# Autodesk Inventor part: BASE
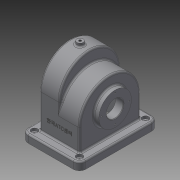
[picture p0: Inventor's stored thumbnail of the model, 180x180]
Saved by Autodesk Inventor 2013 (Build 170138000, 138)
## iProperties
Created: 2017-11
Part Number: BASE
Material: 일반
Document SubType Name: Modeling
Designer: Administrator
Density: 1 g/cm^3
Author: Administrator
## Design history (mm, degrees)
sketch "스케치1"
  geometry: L1 (-58, 0)-(-58, -65); L2 (-58, -65)-(58, -65); L3 (58, -65)-(58, 0); A1 r 58 centre (0, 0) between (58, 0) and (-58, 0); 1 further point
  constraints: 6 end point, 2 point on circle, 2 tangent, 1 centre point, 1 coincident, 1 perpendicular, 1 vertical, 1 vertical alignment
  dimensions: "d0" = 116 diameter of A1; "d3" = 65 distance of L1.start L1.end
extrude "돌출1" new body sketch "스케치1" distance "d4" = 38; taper "d5" = 0 deg
sketch "스케치2"
  geometry: L1 (0, 58)-(65, 58) reference; L2 (65, 58)-(65, -58) reference; L3 (65, -58)-(0, -58) reference; L4 (65, -58)-(65, 58); L5 (65, 58)-(23, 58); L6 (55.666, -58)-(23, -58); L7 (55.666, -58)-(65, -58); A1 r 58 centre (0, 0) between (0, 58) and (0, -58) reference; A2 r 58 centre (23, 0) between (23, 58) and (23, -58); 1 further point
  constraints: 8 end point, 2 collinear, 2 point on circle, 2 tangent, 1 centre point, 1 horizontal alignment, 1 point on line, 1 vertical alignment
  dimensions: "d6" = 116 diameter of A2; "d8" = 42 distance from line of L2 A2.centre
extrude "돌출2" join sketch "스케치2" distance "d9" = 38; taper "d10" = 0 deg
feature "쉘1" dims "d11" = 5
sketch "스케치4"
  geometry: L1 (-71, 111)-(-71, 5) reference; L2 (-71, 5)-(-5, 5) reference; L3 (-5, 5)-(-5, 111) reference; L4 (-5, 111)-(-71, 111) reference; L5 (-76, 0)-(-76, 116) reference; L6 (-76, 116)-(0, 116) reference; L7 (0, 116)-(0, 0) reference; L8 (0, 0)-(-76, 0) reference; L9 (17, 133)-(-93, 133); L10 (-93, 133)-(-93, -17); L11 (-93, -17)-(17, -17); L12 (17, -17)-(17, 133); 1 further point
  constraints: 8 end point, 3 other
  dimensions: "d12" = 110 distance of L9.start L9.end; "d14" = 150 distance of L9.end L10.end (derived)
extrude "돌출3" join sketch "스케치4" distance "d15" = 15; taper "d16" = 0 deg
fillet "모깎기1" dims "d17" = 12
sketch "스케치7"
  geometry: L1 (-80, 75)-(-65, 75) reference; L2 (-65, 75)-(-65, 58) reference; L3 (-65, 58)-(-65, -58) reference; L4 (-65, -58)-(-65, -75) reference; L5 (-65, -75)-(-80, -75) reference; L6 (-80, -75)-(-80, 75) reference; L7 (-65, 58)-(0, 58) reference; L8 (0, -58)-(-65, -58) reference; C1 r 37.5 at (-15, 0); A1 r 58 centre (0, 0) between (0, -58) and (0, 58) reference; 1 further point
  constraints: 1 centre point, 1 horizontal alignment
  dimensions: "d18" = 75 diameter of C1; "d20" = 65 distance from line of L6 C1.centre
extrude "돌출4" join sketch "스케치7" distance "d21" = 9; taper "d22" = 0 deg
sketch "스케치8"
  geometry: L1 (23, 58)-(65, 58) reference; L2 (65, 58)-(65, 75) reference; L3 (65, 75)-(80, 75) reference; L4 (80, 75)-(80, -75) reference; L5 (80, -75)-(65, -75) reference; L6 (65, -75)-(65, -58) reference; L7 (65, -58)-(65, 58) reference; L8 (65, -58)-(23, -58) reference; C1 r 31 at (15, 0); A1 r 58 centre (23, 0) between (23, 58) and (23, -58) reference; 1 further point
  constraints: 1 centre point, 1 horizontal alignment
  dimensions: "d23" = 62 diameter of C1; "d25" = 65 distance from line of L4 C1.centre
extrude "돌출5" join sketch "스케치8" distance "d26" = 10; taper "d27" = 0 deg
sketch "스케치9"
  geometry: L1 (50, -73.909)-(50, 73.909) reference; L2 (50, 73.909)-(65, 73.909) reference; L3 (65, 73.909)-(65, -73.909) reference; L4 (65, -73.909)-(50, -73.909) reference; C1 r 31 at (0, 0) reference; C2 r 16 at (0, 0); 1 further point
  constraints: 1 centre point, 1 coincident
  dimensions: "d28" = 32 diameter of C2
extrude "돌출6" cut sketch "스케치9" stored distance "d30" = 10; taper "d31" = 0 deg
chamfer "모따기1" distance "d32" = 1; stored, may be unused: second distance "d33" = 2, angle "d34" = 45 deg
fillet "모깎기2" dims "d35" = 3
fillet "모깎기3" dims "d36" = 3
hole "구멍1" diameter "d39" = 5; stored, may be unused: countersink angle "d43" = 90 deg, drill point angle "d45" = 118 deg; dims "d37" = 10, "d38" = 10, "d40" = 6, "d41" = 12, "d42" = 5, "d44" = 8
node "작업 평면1"
sketch "스케치11"
  geometry: L1 (55, -66.317)-(55, -59.683) reference; L2 (55, -59.683)-(50, -59.683) reference; L3 (50, -59.683)-(50, 59.683) reference; L4 (50, 59.683)-(55, 59.683) reference; L5 (55, 59.683)-(55, 66.317) reference; L6 (55, 66.317)-(50, 66.317) reference; L7 (50, 66.317)-(50, 73.909) reference; L8 (50, 73.909)-(65, 73.909) reference; L9 (65, 73.909)-(65, -73.909) reference; L10 (65, -73.909)-(50, -73.909) reference; L11 (50, -73.909)-(50, -66.317) reference; L12 (50, -66.317)-(55, -66.317) reference; C1 r 31 at (0, 0) reference; C2 r 17 at (0, 0) reference; C3 r 26 at (0, 0); 2 further points
  constraints: 1 centre point, 1 coincident, 1 horizontal alignment
  dimensions: "d46" = 52 diameter of C3; "d48" = 26 distance of C1.centre point (-26, 0)
hole "구멍2" sketch "스케치11" at (-26, 0) diameter "d49" = 2.459; stored, may be unused: countersink angle "d53" = 90 deg, drill point angle "d55" = 118 deg; dims "d50" = 6, "d51" = 12, "d52" = 5, "d54" = 8
sketch "스케치12"
  geometry: L1 (-65, 74.314)-(-50, 74.314) reference; L2 (-50, 74.314)-(-50, 67.472) reference; L3 (-50, 67.472)-(-55, 67.472) reference; L4 (-55, 67.472)-(-55, 58.528) reference; L5 (-55, 58.528)-(-50, 58.528) reference; L6 (-50, 58.528)-(-50, -58.528) reference; L7 (-50, -58.528)-(-55, -58.528) reference; L8 (-55, -58.528)-(-55, -67.472) reference; L9 (-55, -67.472)-(-50, -67.472) reference; L10 (-50, -67.472)-(-50, -74.314) reference; L11 (-50, -74.314)-(-65, -74.314) reference; L12 (-65, -74.314)-(-65, 74.314) reference; C1 r 37.5 at (0, 0) reference; C2 r 17 at (0, 0) reference; 2 further points
  constraints: 1 horizontal alignment
  dimensions: "d59" = 29 distance of point (29, 0) C1.centre
hole "구멍3" sketch "스케치12" at (29, 0) diameter "d60" = 2.459; stored, may be unused: countersink angle "d64" = 90 deg, drill point angle "d66" = 118 deg; dims "d61" = 6, "d62" = 12, "d63" = 5, "d65" = 8
fillet "모깎기4" dims "d70" = 3
fillet "모깎기5" dims "d71" = 3
node "작업 평면2"
sketch "스케치13"
  geometry: L1 (3, 0)-(3, 116) reference; L2 (3, 0)-(35, 0) reference; L3 (35, 116)-(35, 0) reference; L4 (3, 116)-(35, 116) reference; L5 (73, 116)-(73, 0) reference; L6 (35, 116)-(73, 116) reference; L7 (41, 5.819)-(41, 110.181) reference; L8 (35, 0)-(73, 0) reference; L9 (-9, 95.5)-(-9, 20.5) reference; L10 (86, 27)-(86, 89) reference; L11 (0, 3)-(0, 113) reference; C1 r 6 at (19, 58); 4 further points
  constraints: 1 centre point, 1 horizontal alignment, 1 midpoint, 4 other
  dimensions: "d74" = 19 distance from line of C1.centre L11; "d75" = 12 diameter of C1
extrude "돌출7" join sketch "스케치13" stored distance "d76" = 10; taper "d77" = 0 deg
fillet "모깎기6" dims "d78" = 3
hole "구멍4" diameter "d81" = 4.459; stored, may be unused: countersink angle "d85" = 90 deg, drill point angle "d87" = 118 deg; dims "d79" = 10, "d80" = 10, "d82" = 6, "d83" = 12, "d84" = 5, "d86" = 8
sketch "스케치15"
  geometry: L1 (42.683, -47)-(49.317, -47) reference; L2 (49.317, -47)-(49.317, -42) reference; L3 (49.317, -42)-(55, -42) reference; L4 (58, -45)-(58, -57) reference; L5 (58, -57)-(-52, -57) reference; L6 (-52, -57)-(-52, -45) reference; L7 (-49, -42)-(-43.317, -42) reference; L8 (-43.317, -42)-(-43.317, -47) reference; L9 (-43.317, -47)-(-36.683, -47) reference; L10 (-36.683, -47)-(-36.683, -41.968) reference; L11 (38, -39)-(-32, -39) reference; L12 (42.683, -41.968)-(42.683, -47) reference; L13 (-32, -39)-(-32, 23) reference; L14 (-32, 23)-(0, 23) reference; L15 (0, 23)-(0, 0) reference; L16 (0, 0)-(38, 0) reference; L17 (38, 0)-(38, -39) reference; L18 (-21.887, -13.398)-(27.887, -13.398); L19 (27.887, -13.398)-(27.887, -20.602); L20 (27.887, -20.602)-(-21.887, -20.602); L21 (-21.887, -20.602)-(-21.887, -13.398); L22 (-35, 23)-(-35, -39) reference; A1 r 3 centre (55, -45) between (58, -45) and (55, -42) reference; A2 r 3 centre (-49, -45) between (-49, -42) and (-52, -45) reference; 2 further points
  constraints: 2 midpoint, 4 other
  dimensions: "d88" = 3.60244 distance of point (-21.887, -17) L18.start; "d90" = 7.20489 distance between parallel lines of L20 L18 (derived); "d91" = 49.77477 distance of L18.start L18.end; "d92" = 38 distance from line of point (3, -20.602) L22; "d93" = 40 distance from line of point (-21.887, -17) L5
feature "엠보싱1" sketch "스케치15" dims "d0" = 116, "d3" = 65, "d94" = 0.5, "d95" = 0
node "솔리드1"
mirror "대칭1"
mirror "대칭2"
pattern_circular "원형 패턴1" dims angle "d57" = 360 deg
pattern_circular "원형 패턴2" dims angle "d68" = 360 deg
node "투영된 루프1"
node "투영된 루프2"
node "절단 모서리 투영1"
node "절단 모서리 투영2"
node "절단 모서리 투영4"
node "절단 모서리 투영5"
node "절단 모서리 투영6"
node "절단 모서리 투영7"
node "절단 모서리 투영8"
node "절단 모서리 투영9"
other parameters: "d72" = -144
